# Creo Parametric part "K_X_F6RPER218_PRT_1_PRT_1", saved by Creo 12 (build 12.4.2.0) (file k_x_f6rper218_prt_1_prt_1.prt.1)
Units: Custom; MM, KILOGRAM, SECS

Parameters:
  PTC_WM_ITERATION = "0"
  PTC_WM_VERSION = "-.0"
  PTC_WM_LIFECYCLE_STATE = "In Work"
  PTC_WM_LIFECYCLE = "MO_CADDocument"
  PTC_WM_CREATED_BY = "Maximilian Roepper (Z0017RMS: MO)"
  PTC_WM_CREATED_ON = "18-Sep-26 11:36:42 AM"
  PTC_WM_MODIFIED_BY = "Maximilian Roepper (Z0017RMS: MO)"
  PTC_WM_MODIFIED_ON = "18-Sep-26 11:36:46 AM"
  PDMLINKNUMBER = "PDM000071454886"
  PTC_WM_NAME = "k_x_f6rper218_prt_1_prt_1.prt"
  PTC_WM_NUMBER = "PDM000071454886"

Other parameters: WEIGHT, WEIGHT_FACTOR, WEIGHT_ADD, _MASS_TEMP, _DIFF_TEMP, MC_ERRORS, SUPPLIER

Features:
  1. coordinate system
  2. datum plane "PRT_YZ"
  3. datum plane "PRT_XY"
  4. datum plane "PRT_XZ"
  5. coordinate system
  6. datum axis
  7. datum axis
  8. datum axis
  9. coordinate system
  10. imported feature
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
Other named items: PRT, SIEMENS_MO, DRW_VIEW_ORG, PRT_X, PRT_Y, PRT_Z, CS0, ROUGH_GROB

Layers: 00_STD_CSYS-KSYS, 01_STD_PLANES-EBENEN, 02_STD_AXES-ACHSEN, 03_STD_CSYS-KSYS, 24_IMPORT_FEAT-IMPORT_KE

Surfaces: 9 plane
